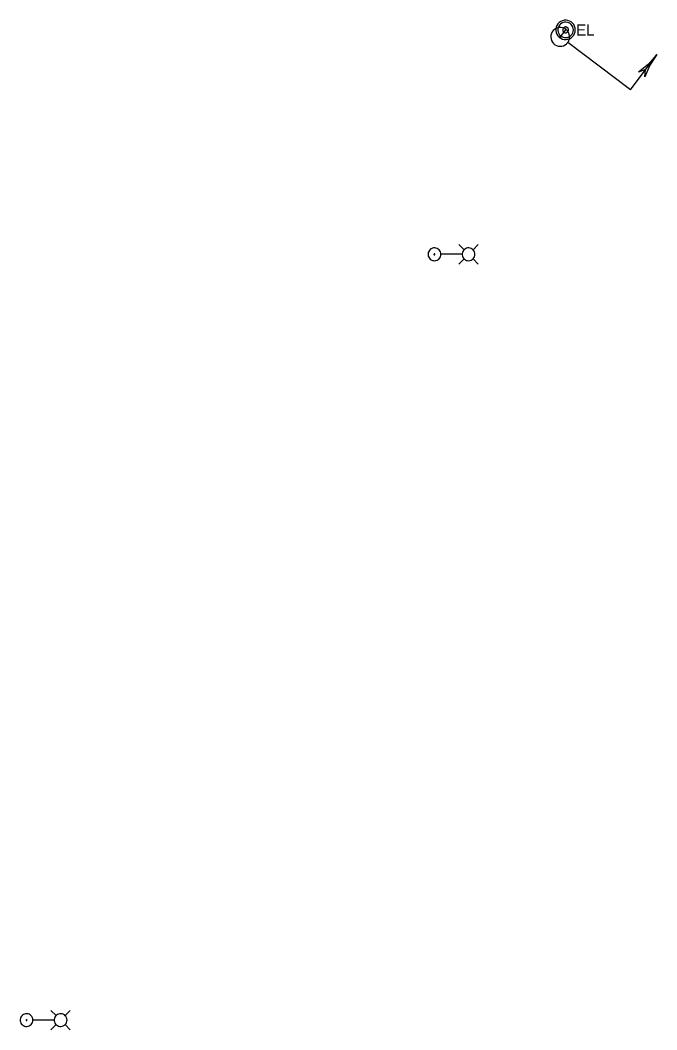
# Model space of a CAD drawing. Extents: x 596028 to 606371, y 330010 to 403088.
# Drawn here: x 604126.9 to 604343.5, y 330010.2 to 330353.5 of the extents above; entities that cross this region are included whole.
import ezdxf

# ---------------------------------------------------------------- set-up
doc = ezdxf.new("R2010")
doc.units = 0
for name, color, linetype in [('E_LTG', 7, 'Continuous'), ('E_SIG', 7, 'Continuous'), ('E_UTL_E', 7, 'Continuous'), ('E_UTL_E_UG', 7, 'Continuous')]:
    doc.layers.add(name, color=color, linetype=linetype)

msp = doc.modelspace()

# ---------------------------------------------------------------- linework, layer by layer
at = {"layer": 'E_LTG'}
for points in [[(604277.92, 330275.43), (604276.14, 330277.2)], [(604280.97, 330275.43), (604282.74, 330277.2)], [(604270.02, 330273.9), (604269.98, 330274.32), (604269.86, 330274.71), (604269.67, 330275.08), (604269.41, 330275.41), (604269.1, 330275.68), (604268.74, 330275.88), (604268.35, 330276.02), (604267.94, 330276.08), (604267.53, 330276.06), (604267.13, 330275.96), (604266.75, 330275.79), (604266.41, 330275.55), (604266.13, 330275.25), (604265.91, 330274.9), (604265.75, 330274.52), (604265.67, 330274.11), (604265.67, 330273.7), (604265.75, 330273.29), (604265.91, 330272.91), (604266.13, 330272.56), (604266.41, 330272.26), (604266.75, 330272.02), (604267.13, 330271.85), (604267.53, 330271.75), (604267.94, 330271.73), (604268.35, 330271.79), (604268.74, 330271.93), (604269.1, 330272.13), (604269.41, 330272.4), (604269.67, 330272.73), (604269.86, 330273.1), (604269.98, 330273.49), (604270.02, 330273.9)], [(604268.01, 330273.9), (604268, 330273.94), (604267.99, 330273.97), (604267.98, 330273.99), (604267.96, 330274.02), (604267.94, 330274.04), (604267.91, 330274.06), (604267.88, 330274.07), (604267.85, 330274.07), (604267.82, 330274.07), (604267.78, 330274.06), (604267.76, 330274.05), (604267.73, 330274.03), (604267.71, 330274.01), (604267.69, 330273.98), (604267.68, 330273.95), (604267.67, 330273.92), (604267.67, 330273.89), (604267.68, 330273.86), (604267.69, 330273.83), (604267.71, 330273.8), (604267.73, 330273.78), (604267.76, 330273.76), (604267.78, 330273.75), (604267.82, 330273.74), (604267.85, 330273.74), (604267.88, 330273.74), (604267.91, 330273.75), (604267.94, 330273.77), (604267.96, 330273.79), (604267.98, 330273.81), (604267.99, 330273.84), (604268, 330273.87), (604268.01, 330273.9)], [(604277.23, 330273.9), (604270.05, 330273.9)], [(604281.62, 330273.9), (604281.58, 330274.32), (604281.46, 330274.71), (604281.27, 330275.08), (604281.02, 330275.41), (604280.7, 330275.68), (604280.35, 330275.88), (604279.96, 330276.02), (604279.55, 330276.08), (604279.13, 330276.06), (604278.73, 330275.96), (604278.35, 330275.79), (604278.02, 330275.55), (604277.73, 330275.25), (604277.51, 330274.9), (604277.36, 330274.52), (604277.28, 330274.11), (604277.28, 330273.7), (604277.36, 330273.29), (604277.51, 330272.91), (604277.73, 330272.56), (604278.02, 330272.26), (604278.35, 330272.02), (604278.73, 330271.85), (604279.13, 330271.75), (604279.55, 330271.73), (604279.96, 330271.79), (604280.35, 330271.93), (604280.7, 330272.13), (604281.02, 330272.4), (604281.27, 330272.73), (604281.46, 330273.1), (604281.58, 330273.49), (604281.62, 330273.9)], [(604277.92, 330272.38), (604276.14, 330270.6)], [(604280.97, 330272.38), (604282.74, 330270.6)], [(604139.11, 330015.03), (604137.33, 330016.8)], [(604142.16, 330015.03), (604143.93, 330016.8)], [(604131.21, 330013.5), (604131.17, 330013.91), (604131.05, 330014.31), (604130.86, 330014.68), (604130.6, 330015), (604130.29, 330015.27), (604129.93, 330015.48), (604129.54, 330015.62), (604129.13, 330015.68), (604128.72, 330015.66), (604128.32, 330015.56), (604127.94, 330015.39), (604127.6, 330015.15), (604127.32, 330014.85), (604127.1, 330014.5), (604126.94, 330014.11), (604126.86, 330013.71), (604126.86, 330013.3), (604126.94, 330012.89), (604127.1, 330012.5), (604127.32, 330012.16), (604127.6, 330011.86), (604127.94, 330011.62), (604128.32, 330011.45), (604128.72, 330011.35), (604129.13, 330011.33), (604129.54, 330011.39), (604129.93, 330011.52), (604130.29, 330011.73), (604130.6, 330012), (604130.86, 330012.33), (604131.05, 330012.69), (604131.17, 330013.09), (604131.21, 330013.5)], [(604129.2, 330013.5), (604129.19, 330013.53), (604129.18, 330013.56), (604129.17, 330013.59), (604129.15, 330013.62), (604129.13, 330013.64), (604129.1, 330013.65), (604129.07, 330013.66), (604129.04, 330013.67), (604129.01, 330013.67), (604128.98, 330013.66), (604128.95, 330013.65), (604128.92, 330013.63), (604128.9, 330013.6), (604128.88, 330013.58), (604128.87, 330013.55), (604128.86, 330013.52), (604128.86, 330013.49), (604128.87, 330013.46), (604128.88, 330013.43), (604128.9, 330013.4), (604128.92, 330013.38), (604128.95, 330013.36), (604128.98, 330013.34), (604129.01, 330013.34), (604129.04, 330013.34), (604129.07, 330013.34), (604129.1, 330013.35), (604129.13, 330013.37), (604129.15, 330013.39), (604129.17, 330013.41), (604129.18, 330013.44), (604129.19, 330013.47), (604129.2, 330013.5)], [(604138.42, 330013.5), (604131.24, 330013.5)], [(604142.81, 330013.5), (604142.77, 330013.91), (604142.65, 330014.31), (604142.46, 330014.68), (604142.21, 330015), (604141.9, 330015.27), (604141.54, 330015.48), (604141.15, 330015.62), (604140.74, 330015.68), (604140.32, 330015.66), (604139.92, 330015.56), (604139.55, 330015.39), (604139.21, 330015.15), (604138.92, 330014.85), (604138.7, 330014.5), (604138.55, 330014.11), (604138.47, 330013.71), (604138.47, 330013.3), (604138.55, 330012.89), (604138.7, 330012.5), (604138.92, 330012.16), (604139.21, 330011.86), (604139.55, 330011.62), (604139.92, 330011.45), (604140.32, 330011.35), (604140.74, 330011.33), (604141.15, 330011.39), (604141.54, 330011.52), (604141.9, 330011.73), (604142.21, 330012), (604142.46, 330012.33), (604142.65, 330012.69), (604142.77, 330013.09), (604142.81, 330013.5)], [(604139.11, 330011.98), (604137.33, 330010.2)], [(604142.16, 330011.98), (604143.93, 330010.2)]]:
    msp.add_lwpolyline(points, dxfattribs=at)
at = {"layer": 'E_SIG'}
for points in [[(604313.19, 330345.91), (604313.51, 330346.43), (604313.72, 330347), (604313.82, 330347.6), (604313.81, 330348.21), (604313.68, 330348.81), (604313.44, 330349.37), (604313.1, 330349.87), (604312.67, 330350.3), (604312.17, 330350.64), (604311.61, 330350.88), (604311.01, 330351.01), (604310.4, 330351.03), (604309.8, 330350.93), (604309.23, 330350.72), (604308.71, 330350.4), (604308.26, 330349.99), (604307.89, 330349.51), (604307.63, 330348.96), (604307.47, 330348.37), (604307.42, 330347.76), (604307.5, 330347.16), (604307.68, 330346.58), (604307.97, 330346.04), (604308.36, 330345.57), (604308.83, 330345.18), (604309.36, 330344.89), (604309.94, 330344.71), (604310.55, 330344.63), (604311.15, 330344.67), (604311.74, 330344.83), (604312.29, 330345.1), (604312.78, 330345.46), (604313.19, 330345.91)], [(604310.82, 330347.69), (604310.85, 330347.73), (604310.86, 330347.77), (604310.87, 330347.82), (604310.87, 330347.86), (604310.86, 330347.91), (604310.84, 330347.95), (604310.82, 330347.99), (604310.78, 330348.02), (604310.74, 330348.05), (604310.7, 330348.07), (604310.66, 330348.08), (604310.61, 330348.08), (604310.56, 330348.07), (604310.52, 330348.05), (604310.48, 330348.03), (604310.45, 330348), (604310.42, 330347.96), (604310.4, 330347.92), (604310.39, 330347.88), (604310.38, 330347.83), (604310.39, 330347.78), (604310.4, 330347.74), (604310.42, 330347.7), (604310.45, 330347.66), (604310.49, 330347.63), (604310.53, 330347.61), (604310.57, 330347.6), (604310.62, 330347.59), (604310.67, 330347.59), (604310.71, 330347.6), (604310.75, 330347.62), (604310.79, 330347.65), (604310.82, 330347.69)], [(604334.53, 330329.89), (604313.23, 330345.88)], [(604334.53, 330329.89), (604343.51, 330341.84)], [(604343.51, 330341.84), (604340.64, 330338.58), (604337.31, 330335.81)], [(604343.51, 330341.84), (604341.18, 330338.18), (604339.45, 330334.21)], [(604339.66, 330336.72), (604337.31, 330335.81)], [(604339.45, 330334.21), (604339.66, 330336.72)], [(604328.56, 330334.37), (604328.56, 330334.37)]]:
    msp.add_lwpolyline(points, dxfattribs=at)
at = {"layer": 'E_UTL_E'}
for points in [[(604315.77, 330350.22), (604315.71, 330350.84), (604315.53, 330351.44), (604315.24, 330352), (604314.86, 330352.5), (604314.38, 330352.91), (604313.84, 330353.22), (604313.25, 330353.43), (604312.63, 330353.51), (604312, 330353.48), (604311.39, 330353.34), (604310.82, 330353.08), (604310.31, 330352.71), (604309.87, 330352.26), (604309.53, 330351.73), (604309.3, 330351.15), (604309.18, 330350.53), (604309.18, 330349.9), (604309.3, 330349.29), (604309.53, 330348.71), (604309.87, 330348.18), (604310.31, 330347.72), (604310.82, 330347.36), (604311.39, 330347.1), (604312, 330346.95), (604312.63, 330346.92), (604313.25, 330347.01), (604313.84, 330347.22), (604314.38, 330347.53), (604314.86, 330347.94), (604315.24, 330348.43), (604315.53, 330348.99), (604315.71, 330349.59), (604315.77, 330350.22)], [(604315.77, 330350.22), (604315.71, 330350.84), (604315.53, 330351.44), (604315.24, 330352), (604314.86, 330352.5), (604314.38, 330352.91), (604313.84, 330353.22), (604313.25, 330353.43), (604312.63, 330353.51), (604312, 330353.48), (604311.39, 330353.34), (604310.82, 330353.08), (604310.31, 330352.71), (604309.87, 330352.26), (604309.53, 330351.73), (604309.3, 330351.15), (604309.18, 330350.53), (604309.18, 330349.9), (604309.3, 330349.29), (604309.53, 330348.71), (604309.87, 330348.18), (604310.31, 330347.72), (604310.82, 330347.36), (604311.39, 330347.1), (604312, 330346.95), (604312.63, 330346.92), (604313.25, 330347.01), (604313.84, 330347.22), (604314.38, 330347.53), (604314.86, 330347.94), (604315.24, 330348.43), (604315.53, 330348.99), (604315.71, 330349.59), (604315.77, 330350.22)], [(604315.11, 330350.22), (604315.06, 330350.72), (604314.92, 330351.2), (604314.69, 330351.65), (604314.38, 330352.04), (604314, 330352.37), (604313.56, 330352.62), (604313.09, 330352.78), (604312.59, 330352.86), (604312.09, 330352.83), (604311.6, 330352.71), (604311.15, 330352.5), (604310.74, 330352.21), (604310.39, 330351.85), (604310.12, 330351.43), (604309.93, 330350.96), (604309.84, 330350.47), (604309.84, 330349.97), (604309.93, 330349.47), (604310.12, 330349.01), (604310.39, 330348.59), (604310.74, 330348.22), (604311.15, 330347.93), (604311.6, 330347.72), (604312.09, 330347.61), (604312.59, 330347.58), (604313.09, 330347.65), (604313.56, 330347.82), (604314, 330348.07), (604314.38, 330348.4), (604314.69, 330348.79), (604314.92, 330349.24), (604315.06, 330349.72), (604315.11, 330350.22)], [(604315.11, 330350.22), (604315.06, 330350.72), (604314.92, 330351.2), (604314.69, 330351.65), (604314.38, 330352.04), (604314, 330352.37), (604313.56, 330352.62), (604313.09, 330352.78), (604312.59, 330352.86), (604312.09, 330352.83), (604311.6, 330352.71), (604311.15, 330352.5), (604310.74, 330352.21), (604310.39, 330351.85), (604310.12, 330351.43), (604309.93, 330350.96), (604309.84, 330350.47), (604309.84, 330349.97), (604309.93, 330349.47), (604310.12, 330349.01), (604310.39, 330348.59), (604310.74, 330348.22), (604311.15, 330347.93), (604311.6, 330347.72), (604312.09, 330347.61), (604312.59, 330347.58), (604313.09, 330347.65), (604313.56, 330347.82), (604314, 330348.07), (604314.38, 330348.4), (604314.69, 330348.79), (604314.92, 330349.24), (604315.06, 330349.72), (604315.11, 330350.22)], [(604313.46, 330350.22), (604313.44, 330350.41), (604313.39, 330350.59), (604313.3, 330350.75), (604313.18, 330350.9), (604313.04, 330351.02), (604312.88, 330351.12), (604312.7, 330351.18), (604312.52, 330351.21), (604312.33, 330351.2), (604312.14, 330351.15), (604311.97, 330351.08), (604311.82, 330350.97), (604311.69, 330350.83), (604311.59, 330350.67), (604311.52, 330350.5), (604311.48, 330350.31), (604311.48, 330350.12), (604311.52, 330349.94), (604311.59, 330349.76), (604311.69, 330349.61), (604311.82, 330349.47), (604311.97, 330349.36), (604312.14, 330349.28), (604312.33, 330349.24), (604312.52, 330349.23), (604312.7, 330349.26), (604312.88, 330349.32), (604313.04, 330349.41), (604313.18, 330349.54), (604313.3, 330349.68), (604313.39, 330349.85), (604313.44, 330350.03), (604313.46, 330350.22)], [(604313.46, 330350.22), (604313.44, 330350.41), (604313.39, 330350.59), (604313.3, 330350.75), (604313.18, 330350.9), (604313.04, 330351.02), (604312.88, 330351.12), (604312.7, 330351.18), (604312.52, 330351.21), (604312.33, 330351.2), (604312.14, 330351.15), (604311.97, 330351.08), (604311.82, 330350.97), (604311.69, 330350.83), (604311.59, 330350.67), (604311.52, 330350.5), (604311.48, 330350.31), (604311.48, 330350.12), (604311.52, 330349.94), (604311.59, 330349.76), (604311.69, 330349.61), (604311.82, 330349.47), (604311.97, 330349.36), (604312.14, 330349.28), (604312.33, 330349.24), (604312.52, 330349.23), (604312.7, 330349.26), (604312.88, 330349.32), (604313.04, 330349.41), (604313.18, 330349.54), (604313.3, 330349.68), (604313.39, 330349.85), (604313.44, 330350.03), (604313.46, 330350.22)]]:
    msp.add_lwpolyline(points, dxfattribs=at)
at = {"layer": 'E_UTL_E_UG'}
msp.add_lwpolyline([(604312.47, 330350.22), (604310.63, 330347.83)], dxfattribs=at)

# ---------------------------------------------------------------- texts
at = {"layer": 'E_UTL_E'}
msp.add_text('EL', height=3.849, dxfattribs=at).set_placement((604316.03, 330348.27))
msp.add_text('EL', height=3.849, dxfattribs=at).set_placement((604316.03, 330348.27))

doc.saveas('drawing.dxf')
